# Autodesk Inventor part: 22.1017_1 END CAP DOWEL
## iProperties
Created: 2009-01
Part Number: 22.1017_1 END CAP DOWEL
Document SubType Name: Modeling
Designer: Administrator
Density: 1.06 g/cm^3
Material: ABS Plastic
Mass: 0.243239 g
Surface Area: 2.18509 cm^2
Volume: 0.229471 cm^3
Author: Administrator
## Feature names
1. Base1
